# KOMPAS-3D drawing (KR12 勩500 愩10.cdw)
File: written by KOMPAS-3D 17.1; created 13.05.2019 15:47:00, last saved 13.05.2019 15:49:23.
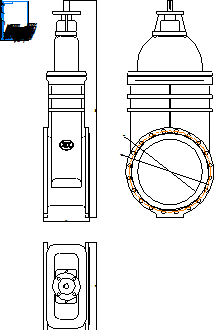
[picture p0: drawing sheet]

Sheet 1: A4, portrait

Title block, sheet 1: name: KR12 Ду500 Ру10; material: Внимание! Данный продукт является объектом авторского права ООО «Торговый Дом АДЛ». / Запрещается изменение, копирование, распространение / (в том числе путем копирования на другие сайты и ресурсы в Интернете) / или любое иное использование информации и объектов без предварительного / согласия правообладателя (ООО «Торговый Дом АДЛ»).; sheets: 1; organisation: ООО "Торговый дом АДЛ"; sheet format: A4

Views: Вид 1, Проекционный вид 2, Проекционный вид 3
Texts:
  user
Dimensions and other numbers on the sheet: 350; 1645,63; 500; 670; 620; 1:1; 1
